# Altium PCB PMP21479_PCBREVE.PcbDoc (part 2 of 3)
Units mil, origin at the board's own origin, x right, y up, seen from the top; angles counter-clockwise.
Board outline 1915.03 x 2932.53 mil, 4 copper layers (Top Layer, Signal Layer 1, Signal Layer 2, Bottom Layer), stack 39.6 mil thick; 137 components, 82 nets, 411 pads, 91 vias.
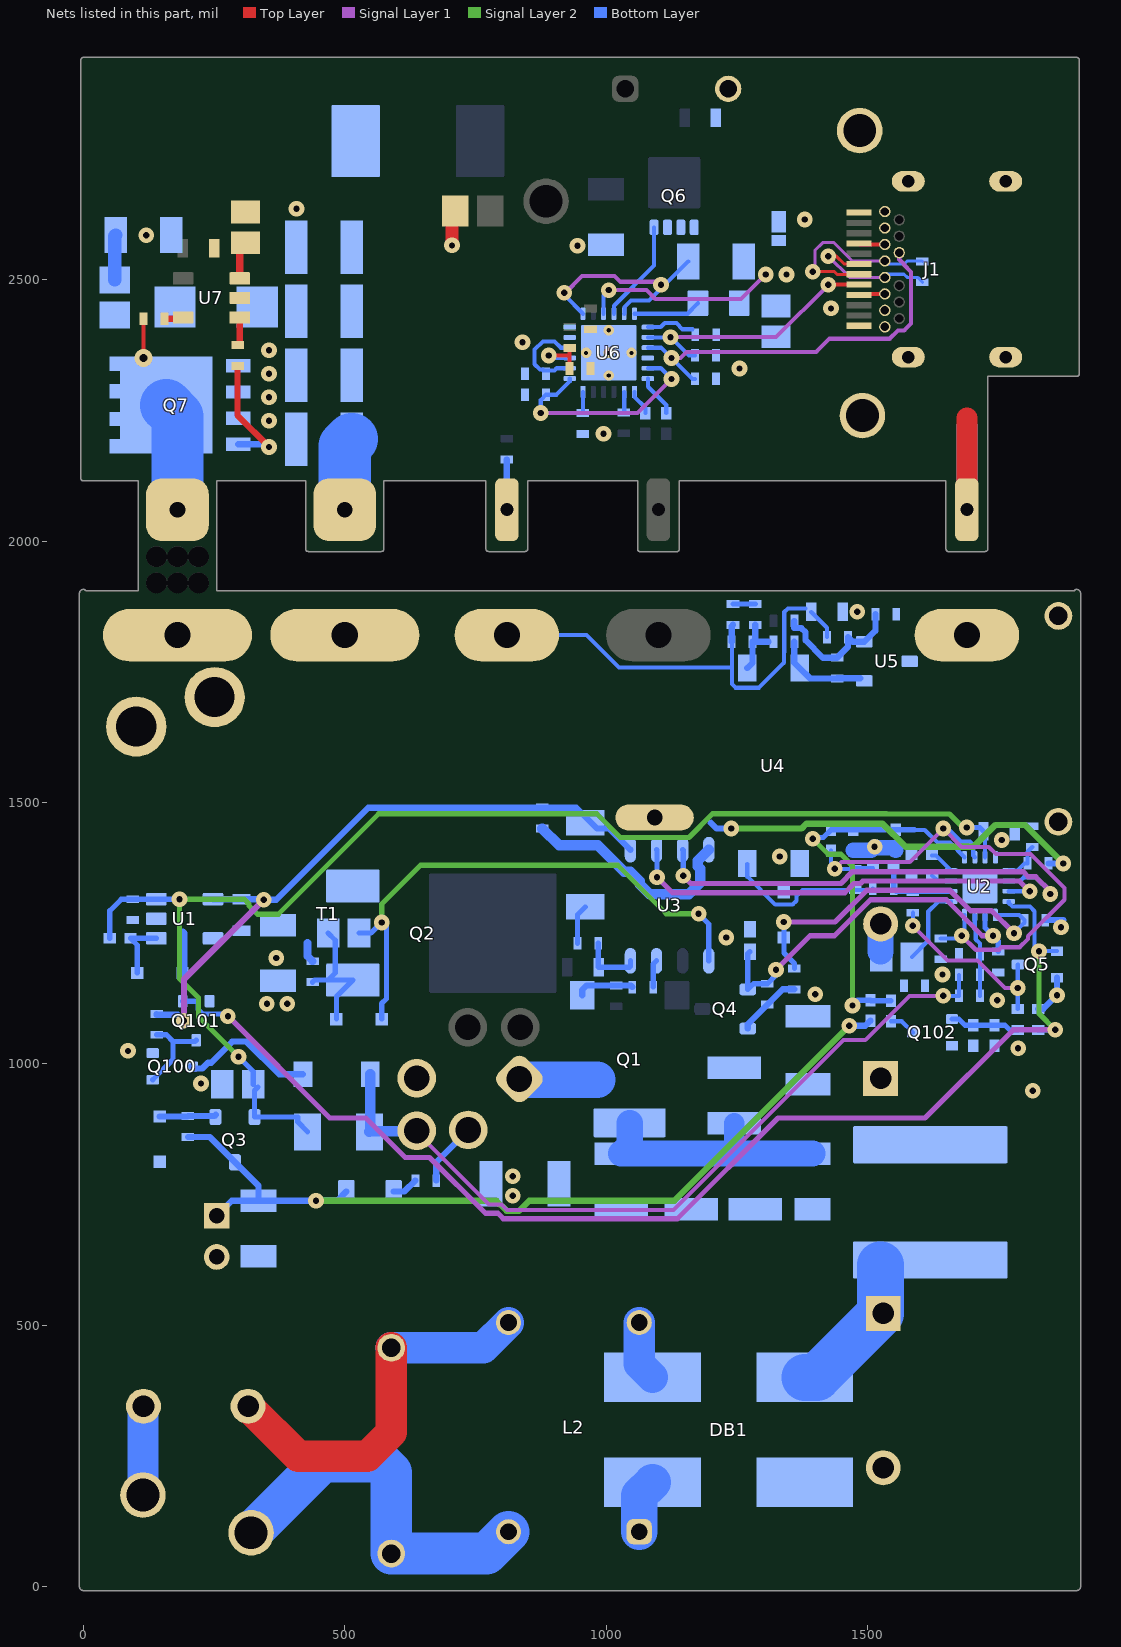
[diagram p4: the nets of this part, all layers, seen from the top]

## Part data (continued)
D3: library part CMP-0029199-1, "Diode, Superfast Rectifier, 200 V, 1 A, 3.5x1.6mm", Manufacturer="Comchip Technology", Supplier Part Number 1=641-1438-1-ND, Value1=1A, Value2=0.95V
D4: library part CMP-0077868-1, "Diode, Standard Recovery Rectifier, 800 V, .2 A, 2x1.4mm", Manufacturer=Rohm, Supplier Part Number 1=RFU02VSM8SCT-ND, Value1=.2A, Value2=2.2V
D5: library part CMP-0005833-2, "Diode, Zener, 15 V, 200 mW, SOD-323", Manufacturer="Diodes Inc.", Power_W=200mW, Supplier Part Number 1=MMSZ5245BS-FDICT-ND, Value1=0.2W
D6: library part CMP-0065112-2, "Diode, TVS, Uni, 18 V, 45 Vc, SOD-323", Manufacturer=Bourns, Supplier Part Number 1=CDSOD323-T18CT-ND, Value1=W
D7: library part CMP-0005884-3, "Diode, Zener, 22 V, 300 mW, SOD-523", Manufacturer="Diodes Inc.", Power_W=300mW, Supplier Part Number 1=BZT52C22T-7DICT-ND, Value1=0.3W
D8: library part CMP-0028829-1, "Diode, Schottky, 30 V, 2 A, 2-XFDFN", Manufacturer="ON Semiconductor", Supplier Part Number 1=NSR20F30NXT5GOSCT-ND, Value1=2A, Value2=0.48V
D9: library part CMP-0005466-2, "Diode, TVS, Bi, 100 V, SMA", Manufacturer=Littelfuse, Power_W=3.3W, Supplier Part Number 1=SMAJ100CALFCT-ND
D100: library part CMP-0029006-2, "Diode, Ultrafast, 100 V, 0.25 A, SOD-323", Manufacturer=Nexperia, Value1=0.25A, Value2=1.4V
D101: library part CMP-0029031-1, "Diode, Switching, 200 V, 0.2 A, SOD-123", Manufacturer="Diodes Inc.", Supplier Part Number 1=BAV21W-FDICT-ND, Value1=0.2A, Value2=1.25V
DB1: "Diode, P-N-Bridge, 600 V, 4 A, Z4-D", Manufacturer="Comchip Technology", Supplier Part Number 1=641-1502-1-ND, Value1=4A, Value2=0.95V
F1: library part CMP-0003561-2, "Fuse, 3.15 A, 250VAC/VDC, TH", Manufacturer=Littelfuse, PartNumber=39213150000, Supplier Part Number 1=F5504CT-ND
J1: library part CMP-0054818-1, "Connector, Receptacle, USB Type C, R/A", Color=Black, Current_A=3A, Manufacturer="Wurth Elektronik", Voltage_V=5V
L1: library part CMP-0084605-1, "Inductor, Shielded, Ferrite, 22 µH, 1.75 A, 0.091 ohm, SMD", Manufacturer="Taiyo Yuden", Value1="0.091 ohm", Value2=1.75A, ValueDisplayed=22µH
L2: library part CMP-0086351-1, "Coupled inductor, 1.3 mH, 0.035 ohm, TH", Manufacturer="Renco Electronics", ValueDisplayed=1.3mH
L3: library part CMP-0062208-1, "Inductor, Shielded, Metal Composite, 330 nH, 21 A, 0.0035 ohm, SMD", Manufacturer=Sumida, Value1="0.003 ohm", Value2=24A, ValueDisplayed=330nH
L100: library part CMP-0086281-1, "Inductor, Wirewound, 1 µH, 0.4 A, 0.091 ohm, SMD", Manufacturer="Taiyo Yuden", Value1="0.091 ohm", Value2=0.4A, ValueDisplayed=1µH
LOGO1: library part IEC_HighVoltage, "IEC 61010-1 High Voltage Warning"
Q1: library part CMP-0086300-1, "MOSFET, N-CH, 700 V, 30 A, PG-SOT223", Alternate Manufacturer=None, Manufacturer="Infineon Technologies", Value1="? ohm", Value2="3.8 nC"
Q2: library part CMP-0079238-1, "MOSFET, N-CH, 600 V, 12 A, DPAK", Alternate Manufacturer=None, Manufacturer="Infineon Technologies", Supplier Part Number 1=IPD60R280P7SAUMA1CT-ND, Value1="? ohm", Value2="18 nC"
Q3: "MOSFET, N-CH, 100 V, 0.17 A, SOT-23", Alternate Manufacturer=None, Manufacturer="Fairchild Semiconductor", Supplier Part Number 1=BSS123NCT-ND, Value1="10 ohm", Value2="1.8 nC"
Q4: library part CMP-0067574-1, "MOSFET, N-CH, 600 V, 0.021 A, AEC-Q101, SOT-23", Alternate Manufacturer=None, Manufacturer="Infineon Technologies", Supplier Part Number 1=BSS126H6327XTSA2CT-ND, Value1="? ohm", Value2="1.4 nC"
Q5: library part CMP-0000643-1, "MOSFET, N-CH, 30 V, 0.18 A, SOT-323", Alternate Manufacturer=None, Manufacturer="NXP Semiconductor", Supplier Part Number 1=568-10508-1-ND, Value1=5, Value2="0.34 nC"
Q6: "MOSFET, N-CH, 30 V, 60 A, DQG0008A", Alternate Manufacturer=None, Manufacturer="Texas Instruments", Supplier Part Number 1=296-39994-1-ND, Value1="0.0032 ohm", Value2="23 nC"
Q7: library part CMP-0001046-2, "MOSFET, N-CH, 150 V, 87 A, PG-TDSON-8", Alternate Manufacturer=None, Manufacturer="Infineon Technologies", Supplier Part Number 1=BSC093N15NS5ATMA1CT-ND, Value2="33 nC"
Q100 Q101 Q102: library part CMP-0000774-1, "MOSFET, N-CH, 60 V, 0.31 A, SOT-323", Alternate Manufacturer=None, Manufacturer="Fairchild Semiconductor", Supplier Part Number 1=2N7002KWCT-ND, Value1=1
R5: library part CMP-0018673-3, "RES, 3.3 M, 5%, 0.25 W, AEC-Q200 Grade 0, 1206", Manufacturer=Vishay-Dale, Power_W=250mW, Supplier Part Number 1=541-3.3MECT-ND, TempCo="200 ppm/C", Tolerance_%=5%, Value2=0.25W, Value_Code=3M30, ValueDisplayed=3.3M
R6: library part CMP-0026721-1, "RES, 100 k, 1%, 0.0625 W, 0402", Manufacturer="Yageo America", Power_W=62.5mW, Supplier Part Number 1=311-100KLRCT-ND, TempCo="100 ppm/C", Tolerance_%=1%, Value2=0.0625W, Value_Code=100k
R7: library part CMP-0026942-3, "RES, 4.7, 5%, 0.063 W, AEC-Q200 Grade 0, 0402", Manufacturer=Vishay-Dale, Power_W=63mW, Supplier Part Number 1=541-4.7JCT-ND, TempCo="200 ppm/C", Tolerance_%=5%, Value2=0.063W, Value_Code=4R70, ValueDisplayed=4.7
R8 R14 R102: library part CMP-0026158-2, "RES, 200 k, 1%, 0.063 W, AEC-Q200 Grade 0, 0402", Manufacturer=Vishay-Dale, Power_W=63mW, Supplier Part Number 1=541-200KLCT-ND, TempCo="100 ppm/C", Tolerance_%=1%, Value2=0.063W, Value_Code=200k
R9: library part CMP-0025997-3, "RES, 130 k, 1%, 0.063 W, AEC-Q200 Grade 0, 0402", Manufacturer=Vishay-Dale, Power_W=63mW, Supplier Part Number 1=541-130KLCT-ND, TempCo="100 ppm/C", Tolerance_%=1%, Value2=0.063W, Value_Code=130k
R10: library part CMP-0026843-3, "RES, 15, 5%, 0.063 W, AEC-Q200 Grade 0, 0402", Manufacturer=Vishay-Dale, Power_W=63mW, Supplier Part Number 1=541-15JCT-ND, TempCo="200 ppm/C", Tolerance_%=5%, Value2=0.063W, Value_Code=15R0, ValueDisplayed=15
R11 R18: library part CMP-0026822-3, "RES, 0, 5%, 0.063 W, AEC-Q200 Grade 0, 0402", Manufacturer=Vishay-Dale, Power_W=63mW, Supplier Part Number 1=541-0.0JCT-ND, TempCo="200 ppm/C", Tolerance_%=5%, Value2=0.063W, Value_Code=0000, ValueDisplayed=0
R12 R16 R100: library part CMP-0026825-5, "RES, 10 k, 5%, 0.063 W, AEC-Q200 Grade 0, 0402", Manufacturer=Vishay-Dale, Power_W=63mW, Supplier Part Number 1=541-10KJCT-ND, TempCo="200 ppm/C", Tolerance_%=5%, Value2=0.063W, Value_Code=10k0, ValueDisplayed=10k
R13: library part CMP-0026399-2, "RES, 48.7 k, 1%, 0.063 W, AEC-Q200 Grade 0, 0402", Manufacturer=Vishay-Dale, Power_W=63mW, Supplier Part Number 1=541-48.7KLCT-ND, TempCo="100 ppm/C", Tolerance_%=1%, Value2=0.063W, Value_Code=48k7, ValueDisplayed=48.7k
R15: library part CMP-0020557-3, "RES, 47, 5%, 0.125 W, AEC-Q200 Grade 0, 0805", Manufacturer=Vishay-Dale, Power_W=125mW, Supplier Part Number 1=541-47ACT-ND, TempCo="200 ppm/C", Tolerance_%=5%, Value2=0.125W, Value_Code=47R0, ValueDisplayed=47
R17: "RES, 1.0 M, 5%, 0.063 W, 0402", Manufacturer=Vishay-Dale, Power_W=0.063, Supplier Part Number 1=541-1.0MJCT-ND, TempCo="200 ppm/C", Tolerance_%=5, Value1=5%, Value2=0.063W, Value_Code=1M00, ValueDisplayed=1.0M
R19: library part CMP-0026095-2, "RES, 1.78 k, 1%, 0.063 W, AEC-Q200 Grade 0, 0402", Manufacturer=Vishay-Dale, Power_W=63mW, Supplier Part Number 1=541-1.78KLCT-ND, TempCo="100 ppm/C", Tolerance_%=1%, Value2=0.063W, Value_Code=1k78, ValueDisplayed=1.78k
R20: library part CMP-0026453-2, "RES, 56.2 k, 1%, 0.063 W, AEC-Q200 Grade 0, 0402", Manufacturer=Vishay-Dale, Power_W=63mW, Supplier Part Number 1=541-56.2KLCT-ND, TempCo="100 ppm/C", Tolerance_%=1%, Value2=0.063W, Value_Code=56k2, ValueDisplayed=56.2k
R21: library part CMP-0017277-2, "RES, 0.15, 1%, 0.5 W, 1206", Manufacturer=Panasonic, Power_W=500mW, Supplier Part Number 1=P16006CT-ND, TempCo="250 ppm/C", Tolerance_%=1%, Value2=0.5W, Value_Code=R150, ValueDisplayed=0.15
R22: library part CMP-0026665-1, "RES, 137 k, 1%, 0.1 W, AEC-Q200 Grade 0, 0402", Manufacturer=Panasonic, Power_W=100mW, Supplier Part Number 1=P137KLCT-ND, TempCo="100 ppm/C", Tolerance_%=1%, Value2=0.1W, Value_Code=137k
R23: library part CMP-0026004-3, "RES, 13.3 k, 1%, 0.063 W, AEC-Q200 Grade 0, 0402", Manufacturer=Vishay-Dale, Power_W=63mW, Supplier Part Number 1=541-13.3KLCT-ND, TempCo="100 ppm/C", Tolerance_%=1%, Value2=0.063W, Value_Code=13k3, ValueDisplayed=13.3k
R24: library part CMP-0025974-3, "RES, 118, 1%, 0.063 W, AEC-Q200 Grade 0, 0402", Manufacturer=Vishay-Dale, Power_W=63mW, Supplier Part Number 1=541-118LCT-ND, TempCo="100 ppm/C", Tolerance_%=1%, Value2=0.063W, Value_Code=118R, ValueDisplayed=118
R25 R31: library part CMP-0026669-1, "RES, 150 k, 1%, 0.1 W, AEC-Q200 Grade 0, 0402", Manufacturer=Panasonic, Power_W=100mW, Supplier Part Number 1=P150KLCT-ND, TempCo="100 ppm/C", Tolerance_%=1%, Value2=0.1W, Value_Code=150k
R26: library part CMP-0026329-2, "RES, 3.01 k, 1%, 0.063 W, AEC-Q200 Grade 0, 0402", Manufacturer=Vishay-Dale, Power_W=63mW, Supplier Part Number 1=541-3.01KLCT-ND, TempCo="100 ppm/C", Tolerance_%=1%, Value2=0.063W, Value_Code=3k01, ValueDisplayed=3.01k
R27: library part CMP-0026022-3, "RES, 150, 1%, 0.063 W, AEC-Q200 Grade 0, 0402", Manufacturer=Vishay-Dale, Power_W=63mW, Supplier Part Number 1=541-150LCT-ND, TempCo="100 ppm/C", Tolerance_%=1%, Value2=0.063W, Value_Code=150R, ValueDisplayed=150
R28: library part CMP-0026196-2, "RES, 24.9 k, 1%, 0.063 W, AEC-Q200 Grade 0, 0402", Manufacturer=Vishay-Dale, Power_W=63mW, Supplier Part Number 1=541-24.9KLCT-ND, TempCo="100 ppm/C", Tolerance_%=1%, Value2=0.063W, Value_Code=24k9, ValueDisplayed=24.9k
R29: library part CMP-0026859-2, "RES, 1.0 M, 5%, 0.063 W, AEC-Q200 Grade 0, 0402", Manufacturer=Vishay-Dale, Power_W=63mW, Supplier Part Number 1=541-1.0MJCT-ND, TempCo="200 ppm/C", Tolerance_%=5%, Value2=0.063W, Value_Code=1M00, ValueDisplayed=1.0M
R30: library part CMP-0026327-2, "RES, 39.2 k, 1%, 0.063 W, AEC-Q200 Grade 0, 0402", Manufacturer=Vishay-Dale, Power_W=63mW, Supplier Part Number 1=541-39.2KLCT-ND, TempCo="100 ppm/C", Tolerance_%=1%, Value2=0.063W, Value_Code=39k2, ValueDisplayed=39.2k
R32 R47: library part CMP-0026027-3, "RES, 15.0 k, 1%, 0.063 W, AEC-Q200 Grade 0, 0402", Manufacturer=Vishay-Dale, Power_W=63mW, Supplier Part Number 1=541-15.0KLCT-ND, TempCo="100 ppm/C", Tolerance_%=1%, Value2=0.063W, Value_Code=15k0, ValueDisplayed=15.0k
R33: library part CMP-0026435-2, "RES, 511 k, 1%, 0.063 W, AEC-Q200 Grade 0, 0402", Manufacturer=Vishay-Dale, Power_W=63mW, Supplier Part Number 1=541-511KLCT-ND, TempCo="100 ppm/C", Tolerance_%=1%, Value2=0.063W, Value_Code=511k
R34: "RES, 0.005, 1%, 0.25 W, 1206", Manufacturer=Vishay-Dale, Power_W=0.25, Supplier Part Number 1=WSLC-.005CT-ND, TempCo="110 ppm/C", Tolerance_%=1, Value1=1%, Value2=0.25W, Value_Code=5L000, ValueDisplayed=0.005
R35: "RES, 100, 5%, 0.063 W, 0402", Manufacturer=Vishay-Dale, Power_W=0.063, Supplier Part Number 1=541-100JCT-ND, TempCo="200 ppm/C", Tolerance_%=5, Value1=5%, Value2=0.063W, Value_Code=100R, ValueDisplayed=100
R36: "RES, 100 k, 1%, 0.063 W, 0402", Manufacturer=Vishay-Dale, Power_W=0.063, Supplier Part Number 1=541-100KLCT-ND, TempCo="100 ppm/C", Tolerance_%=1, Value1=1%, Value2=0.063W, Value_Code=100k
R37: "RES, 140 k, 1%, 0.063 W, 0402", Manufacturer=Vishay-Dale, Power_W=0.063, Supplier Part Number 1=541-140KLCT-ND, TempCo="100 ppm/C", Tolerance_%=1, Value1=1%, Value2=0.063W, Value_Code=140k
R38: "RES, 86.6 k, 1%, 0.063 W, 0402", Manufacturer=Vishay-Dale, Power_W=0.063, Supplier Part Number 1=541-86.6KLCT-ND, TempCo="100 ppm/C", Tolerance_%=1, Value1=1%, Value2=0.063W, Value_Code=86k6, ValueDisplayed=86.6k
R39: "RES, 120, 0.1%, 0.125 W, 0805", Manufacturer="Susumu Co Ltd", Power_W=0.125, Supplier Part Number 1=RG20P120BCT-ND, TempCo="25 ppm/C", Tolerance_%=0.1, Value1=0.1%, Value2=0.125W, Value_Code=120R, ValueDisplayed=120
R40: library part CMP-0025702-4, "RES, 10 M, 5%, 0.1 W, AEC-Q200 Grade 0, 0603", Manufacturer=Vishay-Dale, Power_W=100mW, Supplier Part Number 1=541-10MGCT-ND, TempCo="200 ppm/C", Tolerance_%=5%, Value2=0.1W, Value_Code=10M0, ValueDisplayed=10M
R41: library part CMP-0018603-3, "RES, 1.0 k, 5%, 0.25 W, AEC-Q200 Grade 0, 1206", Manufacturer=Vishay-Dale, Power_W=250mW, Supplier Part Number 1=541-1.0KECT-ND, TempCo="200 ppm/C", Tolerance_%=5%, Value2=0.25W, Value_Code=1k00, ValueDisplayed=1.0k
R42 R43: library part CMP-0026827-3, "RES, 10, 5%, 0.063 W, AEC-Q200 Grade 0, 0402", Manufacturer=Vishay-Dale, Power_W=63mW, Supplier Part Number 1=541-10JCT-ND, TempCo="200 ppm/C", Tolerance_%=5%, Value2=0.063W, Value_Code=10R0, ValueDisplayed=10
R44 R45: library part CMP-0027004-2, "RES, 0, 5%, 0.063 W, 0402", Manufacturer="Yageo America", Power_W=63mW, Supplier Part Number 1=311-0.0JRCT-ND, TempCo="200 ppm/C", Tolerance_%=5%, Value2=0.063W, Value_Code=0000, ValueDisplayed=0
R46: library part CMP-0026510-2, "RES, 69.8 k, 1%, 0.063 W, AEC-Q200 Grade 0, 0402", Manufacturer=Vishay-Dale, Power_W=63mW, Supplier Part Number 1=541-69.8KLCT-ND, TempCo="100 ppm/C", Tolerance_%=1%, Value2=0.063W, Value_Code=69k8, ValueDisplayed=69.8k
R101: library part CMP-0025950-3, "RES, 100 k, 1%, 0.063 W, AEC-Q200 Grade 0, 0402", Manufacturer=Vishay-Dale, Power_W=63mW, Supplier Part Number 1=541-100KLCT-ND, TempCo="100 ppm/C", Tolerance_%=1%, Value2=0.063W, Value_Code=100k
R103: library part CMP-0026280-2, "RES, 301 k, 1%, 0.063 W, AEC-Q200 Grade 0, 0402", Manufacturer=Vishay-Dale, Power_W=63mW, Supplier Part Number 1=541-301KLCT-ND, TempCo="100 ppm/C", Tolerance_%=1%, Value2=0.063W, Value_Code=301k
R104: library part CMP-0026100-2, "RES, 1.00 M, 1%, 0.063 W, AEC-Q200 Grade 0, 0402", Manufacturer=Vishay-Dale, Power_W=63mW, Supplier Part Number 1=541-1.00MLCT-ND, TempCo="100 ppm/C", Tolerance_%=1%, Value2=0.063W, Value_Code=1M00, ValueDisplayed=1.00M
RT1: library part CMP-0002532-2, "Thermistor NTC, 100k ohm, 5%, 0805", Manufacturer=MuRata, Power_W=200mW, Supplier Part Number 1=490-2451-1-ND, Tolerance_%=5%
T1: library part CMP-0081439-3, "Transformer, 110 uH, TH", Manufacturer="Renco Electronics", ValueDisplayed=110µH
TP1 TP4: library part CMP-0055148-1, "Test Point, Multipurpose, Black, TH", Color=Black, Manufacturer=Keystone, PartNumber=5011, Supplier Part Number 1=36-5011-ND
TP2: library part CMP-0055149-1, "Test Point, Multipurpose, White, TH", Color=White, Manufacturer=Keystone, PartNumber=5012, Supplier Part Number 1=36-5012-ND
TP3 TP5: library part CMP-0055147-1, "Test Point, Multipurpose, Red, TH", Color=Red, Manufacturer=Keystone, PartNumber=5010, Supplier Part Number 1=36-5010-ND
U1: library part CMP-0066933-1, "50-mA 40-V Voltage-Tracking LDO With 5-mV Tracking Tolerance, DBV0005A (SOT-23-5)", Alternate Manufacturer="Texas Instruments"
U2: library part CMP-0014005-4, "Active-Clamp Flyback Controller, RTE0016C (WQFN-16)", Alternate Manufacturer="Texas Instruments", Alternate PartNumber=UCC28780RTE
U3: library part CMP-0065069-2, "620-V High-Side Low-Side Gate Driver with 0.5/1.0A Peak Output and RobustDrive, D0008B (SOIC-8)", Alternate Manufacturer="Texas Instruments", Alternate PartNumber=UCC27710D
U4: library part CMP-0006160-3, "Optocoupler, 5 kV, 63-125% CTR, SMT", Manufacturer=Vishay-Semiconductor, Supplier Part Number 1=VOL618A-2TCT-ND, Voltage_Isolation_Vrms=5kV
U5: library part CMP-0066199-1, "2.5V Low Iq Adjustable Precision Shunt Regulator, DBZ0003A (SOT-23-3)", Alternate Manufacturer="Texas Instruments"
U6: "USB Type-C and USB PD Source Controller, RGE0024H (VQFN-24)", Alternate Manufacturer="Texas Instruments", Alternate PartNumber=TPS25740BRGET
U7: library part CMP-0013047-3, "High-Frequency Multi-Mode Synchronous Rectifier Controller, DBV0005A (SOT-23-5)", Alternate Manufacturer="Texas Instruments", Alternate PartNumber=UCC24612-2DBVR

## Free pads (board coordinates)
  oval 285x100 hole 50 slot 200 at 0 deg: 0(180,1820) 0(500,1820)
  oval 200x100 hole 50 slot 120 at 0 deg: 0(810,1820) 0(1100,1820) 0(1690,1820)
  oval 150x50 hole 30 slot 110 at 0 deg: 0(1092.72,1471.05)
  round 40 hole 40 unplated: 1(140,1920) 1(140,1970) 1(180,1920) 1(180,1970) 1(220,1920) 1(220,1970)
  rrect50% 120x120 hole 30: 2(180,2060) 2(500,2060)
  rrect50% 45x120 hole 25: 2(810,2060) 2(1100,2060) 2(1690,2060)

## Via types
v1: diameter 30, hole 12, Top Layer to Bottom Layer, 44 vias
v2: diameter 30, hole 12, Top Layer to Bottom Layer, tented both sides, 31 vias
v3: diameter 19.68, hole 7.87, Top Layer to Bottom Layer, 11 vias
v4: diameter 30, hole 12, Top Layer to Bottom Layer, tented bottom, 2 vias
v5: diameter 19.68, hole 7.87, Top Layer to Bottom Layer, tented both sides, 1 vias
v6: diameter 30, hole 12, Top Layer to Bottom Layer, tented top, 1 vias
v7: diameter 34, hole 16, Top Layer to Bottom Layer, 1 vias

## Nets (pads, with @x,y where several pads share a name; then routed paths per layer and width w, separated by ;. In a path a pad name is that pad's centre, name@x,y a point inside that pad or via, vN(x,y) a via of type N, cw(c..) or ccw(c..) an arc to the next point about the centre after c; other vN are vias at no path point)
CC1: C33.1 J1.A5 U6.2 | length 506.1
  Top Layer w8: v1(1425,2490) 1425.47,2490.47 J1.A5@1483.46,2490.47
  Signal Layer 1 w8: v1(1123.21,2390) 1325,2390 v1(1425,2490)
  Bottom Layer w8: U6.2@1079.8,2389.53 v1@1122.74,2389.53 ; v1(1123.21,2390) 1158.21,2355 C33.1@1170,2355
CC2: C34.1 J1.B5 U6.3 | length 745.5
  Signal Layer 1 w8: v1(1125,2350) 1141.99,2350 1153.87,2361.87 1401.7,2361.87 1426.89,2387.06 1542.47,2387.06 1558.22,2402.81 1570.03,2402.81 1583.33,2416.11 1583.33,2514.8 1569.62,2528.51 1569.62,2529.8 1560.63,2538.78 J1.B5@1560.63,2551.5
  Bottom Layer w8: U6.3@1079.8,2369.84 1105.16,2369.84 v1(1125,2350) 1165,2310 C34.1@1170,2310
CTL1: R47.2 U6.6 | length 80.4
  Bottom Layer w8: U6.6@1079.8,2310.79 1079.8,2295.2 1115,2260 R47.2@1115,2245
CTL2: R46.2 U6.7 | length 48.8
  Bottom Layer w8: U6.7@1054.21,2285.2 1054.21,2275.79 1075,2255 R46.2@1075,2245
CTL3: R45.1 U6.8 | length 39.7
  Bottom Layer w8: R45.1@1034.53,2245.47 U6.8@1034.53,2285.2
DN: J1.A7 J1.B7 R35.1 | length 273.9
  Top Layer w6: v1(1425,2545) 1440,2545 1455.16,2529.84 J1.A7@1483.46,2529.84
  Signal Layer 1 w6: v1(1425,2545) 1465.75,2504.25 J1.B7@1533.07,2504.25
  Bottom Layer w6: J1.B7@1533.07,2504.25 1533.07,2510.2 1569.62,2510.2 1575.57,2504.25 1595.75,2504.25 R35.1@1605,2495
DP: J1.A6 J1.B6 R35.2 | length 369.1
  Top Layer w6: v1(1395,2515) 1395.87,2515.87 1435.72,2515.87 1441.43,2510.16 J1.A6@1483.46,2510.16
  Signal Layer 1 w6: v1(1395,2515) 1399.13,2519.13 1399.13,2555.72 1414.28,2570.87 1435.72,2570.87 1470.84,2535.75 J1.B6@1533.07,2535.75
  Bottom Layer w6: J1.B6@1533.07,2535.75 1533.07,2529.8 1569.62,2529.8 1575.57,2535.75 1604.25,2535.75 R35.2@1605,2535
FB: C14.2 R30.1 R33.2 U2.10 | length 141.8
  Bottom Layer w10: C14.2@1550,1365 R30.1@1550,1335 1555,1330 1580,1330 1625,1330 ; 1625.16,1330.16 U2.10@1659.88,1330.16
ICGND: C10.2 C12.2 C13.2 C21.2 C23.2 C101.2 Q102.2 R8.1 R9.1 R13.1 R18.2 R23.1 R102.1 U2.16 U2.17@1715,1340 | length 86.9
  Bottom Layer w30: R13.1@1472.39,1408.45 1506.9,1408.45 v1(1513.45,1415) 1515.19,1413.26 1549.2,1413.26 C13.2@1553.89,1408.57
  other v1: 1787.96,1029.71 1747.99,1121.82 1643.2,1170.91
  other v2: 1756.67,1428.13
NetC1_1: C1.1 DB1.1 L1.1 | length 288.1
  Bottom Layer w90: DB1.1@1379.89,400.39 1402.76,400.39 1525,522.64 L1.1@1525,615
NetC3_1: C3.1 F1.1 L2.4 | length 738.6
  Top Layer w60: F1.1@315,345 410.72,249.28 543.35,249.28 589,294.93 C3.1@589,456.85
  Bottom Layer w60: C3.1@589,456.85 765.04,456.85 L2.4@813.19,505
NetC3_2: C3.2 L2.2 TP2.1 | length 729.4
  Bottom Layer w80: TP2.1@321,103 456.71,238.71 568.77,238.71 589,218.47 C3.2@589,63.15 771.34,63.15 L2.2@813.19,105
NetC6_2: C6.2 C7.2 C8.2 C9.2 Q1.2 R5.1 | length 492
  Bottom Layer w40: C6.2@1240,828.15 1245,833.15 C8.2@1245,886.35
  Bottom Layer w50: Q1.2@1045,887.11 1045,844.23 C9.2@1028.92,828.15 1240,828.15 R5.1@1395,828.15
NetC11_1: C11.1 R7.2 U3.8 | length 118
  Bottom Layer w10: R7.2@985,1230.73 985,1185.58 C11.1@985.79,1184.79 1044.47,1184.79 1046.32,1186.65 U3.8@1046.32,1197.06
NetC13_1: C13.1 R13.2 R14.1 R101.2 R104.1 U2.13 | length 762.8
  Signal Layer 2 w10: v2(1395,1430.49) 1424.66,1400.84 1448.99,1400.84 1471.12,1378.71 v2(1471.12,1111.61)
  Bottom Layer w8: 1589.76,1447.57 1609.43,1447.57 1633.87,1423.13 1657.46,1423.13 U2.13@1685.47,1395.12
  Bottom Layer w10: v2(1395,1430.49) 1397.39,1432.88 1415.31,1432.88 R14.1@1430,1447.57 1430.25,1447.82 R13.2@1472.39,1447.82 1472.52,1447.94 C13.1@1553.89,1447.94 1554.26,1447.57 1589.76,1447.57 ; v2(1471.12,1111.61) 1481.32,1121.82 R104.1@1505.5,1121.82 1506.46,1120.86 R101.2@1545,1120.86
NetC17_2: C17.2 C18.1 C102.2 D1.2 Q2.3 R16.1 R19.2 R21.2 U1.2 U1.5 U3.4 | length 1333.6
  Signal Layer 2 w12: v2(1239.29,1450) 1373.67,1450 1383.04,1459.37 1528.58,1459.37 1572.94,1415 1702.71,1415 1744.71,1457.01 1800.85,1457.01 v2(1874.55,1383.31)
  Bottom Layer w12: 1200.2,1461.13 1211.32,1450 v2(1239.29,1450) ; R19.2@1846.14,1383.31 v2(1874.55,1383.31)
  Bottom Layer w15: 428.94,1231.41 428.94,1205.79 R16.1@438.51,1196.22
  Bottom Layer w20: D1.2@189.57,1173.62 189.57,1249.14 ; C102.2@877.65,1450 909.81,1417.84 983.77,1417.84 1034.43,1367.18 1046.32,1367.18 1064.38,1349.12 1064.38,1343.26 1083.64,1324 1158.06,1324 1180.13,1346.07 1180.13,1373.3 1175.49,1377.94 1175.49,1388.83 U3.4@1196.32,1409.66
NetC20_2: C20.2 R20.1 R23.2 U2.7 | length 159
  Bottom Layer w8: U2.7@1705.16,1284.88 1705.16,1257.85 1706.87,1256.13 1706.87,1238.13 1715,1230 R23.2@1715,1210 R20.1@1715,1170 C20.2@1715,1130
NetC21_1: C21.1 R19.1 U2.1 | length 76.6
  Bottom Layer w8: U2.1@1770.12,1369.53 1786.65,1369.53 1800.43,1383.31 R19.1@1806.14,1383.31 1806.14,1405.67 C21.1@1815,1414.54
NetC23_1: C23.1 D7.1 Q4.1 R22.2 U2.6 | length 729.1
  Signal Layer 1 w10: v2(1325,1180) 1390,1245 1436.83,1245 1505.81,1313.98 1650.44,1313.98 1719.42,1245 v1(1740,1245)
  Bottom Layer w10: D7.1@1275,1214.56 1270.8,1210.36 Q4.1@1270.8,1142.32 1281.76,1153.28 R22.2@1308.42,1153.28 1325,1169.86 v2(1325,1180) ; U2.6@1724.84,1284.88 1724.84,1260.16 v1(1740,1245) 1750,1235 C23.1@1750,1215
NetC24_2: C24.2 D6.1 R24.1 U2.5 | length 689.8
  Signal Layer 1 w10: v2(1339.48,1271.3) 1437.85,1271.3 1498.4,1331.85 1657.85,1331.85 1696.74,1292.96 1737.04,1292.96 v4(1780,1250)
  Bottom Layer w8: U2.5@1744.53,1284.88 1790.12,1284.88 C24.2@1800,1275 1800,1270 v4(1780,1250)
  Bottom Layer w10: v2(1339.48,1271.3) 1340,1270.77 D6.1@1340,1241.79 1340,1211.85 1360,1191.85 R24.1@1360,1182.4
NetC25_2: C25.2 R27.2 | length 42.4
  Bottom Layer w10: C25.2@1242.59,1879.64 R27.2@1285,1879.64
NetC27_1: C27.1 R25.1 R28.2 R31.1 U5.2 | length 271.8
  Bottom Layer w12: R28.2@1360,1847.15 1360,1833.47 1373.25,1833.47 1381.37,1825.35 1381.37,1810.29 1414.66,1777.01 C27.1@1441.58,1777.01 1462.55,1797.97 R25.1@1462.55,1816.15 1471.43,1807.27 U5.2@1493.88,1807.27 1515,1828.39 R31.1@1515,1860
NetC27_2: C27.2 R32.1 U4.2 U5.1 | length 179.5
  Bottom Layer w12: R32.1@1360,1807.6 1360,1767.01 U4.2@1370,1757.01 1390,1737.01 C27.2@1441.58,1737.01 1442.17,1737.6 U5.1@1486.19,1737.6
NetC30_1: C30.1 U6.5 U6.13 | length 431
  Signal Layer 1 w8: v1(875,2245) 1060,2245 v1(1125,2310)
  Bottom Layer w8: v1(875,2245) 875,2270 C30.1@885,2280 905,2280 930.2,2305.2 U6.13@930.2,2310.79 ; U6.5@1079.8,2330.47 1104.53,2330.47 v1(1125,2310)
NetC31_1: C31.1 U6.14 U6.16 | length 181.6
  Bottom Layer w8: U6.14@930.2,2330.47 905.47,2330.47 901.13,2326.13 878.87,2326.13 878.87,2328.13 873.17,2328.13 863.13,2338.17 863.13,2366.13 878.87,2381.87 901.13,2381.87 913.16,2369.84 U6.16@930.2,2369.84
NetC32_1: C32.1 U6.1 | length 93.3
  Bottom Layer w8: U6.1@1079.8,2409.21 1104.42,2409.21 1112.08,2416.87 1134.34,2416.87 1146.21,2405 C32.1@1165,2405
NetC41_2: C41.2 R41.2 | length 86.3
  Bottom Layer w25: C41.2@60,2499.49 60,2583.15 R41.2@61.85,2585
NetC42_2: C42.2 U7.3 | length 53.3
  Top Layer w15: U7.3@299.13,2502.4 C42.2@299.13,2555.67
NetC100_1: C100.1 Q5.3 R33.1 | length 360
  Signal Layer 1 w8: v2(1586.62,1264) 1652.84,1197.78 1710.04,1197.78 1762.82,1145 v2(1787.15,1145)
  Bottom Layer w8: v2(1586.62,1264) 1586.62,1288.82 R33.1@1586.76,1288.97 ; C100.1@1787.15,1105 v2(1787.15,1145) 1787.15,1189.55 Q5.3@1787.6,1190
NetC101_1: C101.1 Q102.1 R102.2 R103.1 | length 134.3
  Bottom Layer w10: Q102.1@1661.57,1085.59 1674.36,1085.59 1686.29,1073.66 C101.1@1702.42,1073.66 R102.2@1742.95,1073.66 1763.07,1073.66 1772.1,1064.63 R103.1@1787.15,1064.63
NetD1_1: D1.1 R6.1 U1.1 | length 121.5
  Bottom Layer w10: D1.1@102.95,1173.62 102.95,1227.17 R6.1@90,1240.12 U1.1@139.61,1240.12
NetD2_1: D2.1 R7.1 | length 75.6
  Bottom Layer w10: R7.1@945,1230.73 945,1285.1 D2.1@960,1300.1
NetD4_2: D4.2 R11.2 | length 50.2
  Bottom Layer w12: D4.2@593.46,755.78 614.09,755.78 R11.2@635,776.69
NetD5_1: D5.1 Q3.1 R17.2 | length 108.3
  Bottom Layer w12: D5.1@146.26,899.33 199.33,899.33 R17.2@200,900 250.91,900 Q3.1@253.31,902.4
NetD100_1: D100.1 R15.1 U3.5 | length 1052.9
  Signal Layer 2 w10: v2(570.53,1270.47) 570.53,1305.36 645.08,1379.92 1022.19,1379.92 1115.06,1287.05 v2(1176.81,1287.05)
  Bottom Layer w10: R15.1@527.22,1250 550.05,1250 v2(570.53,1270.47) 579.7,1261.3 579.7,1124.51 570.53,1115.34 D100.1@570.53,1085.59 ; v2(1176.81,1287.05) 1196.32,1267.54 U3.5@1196.32,1197.06
NetD100_2: D100.2 Q2.1 R15.2 R16.2 | length 267.6
  Bottom Layer w10: R16.2@438.51,1156.22 442.53,1160.24 Q2.1@468.54,1160.24 ; R15.2@468.16,1250 481.92,1236.24 481.92,1173.62 Q2.1@468.54,1160.24 ; D100.2@483.91,1085.59 483.91,1128.51 Q2.1@515.64,1160.24 Q2.1@468.54,1160.24
NetD101_1: D101.1 Q100.3 | length 262
  Bottom Layer w12: Q100.3@207.4,995 212.16,990.24 213.04,991.13 227.25,991.13 238.34,1002.21 244.33,1002.21 284.65,1042.53 311.87,1042.53 374.41,980 D101.1@419.84,980
NetDB1_2: DB1.2 L2.3 | length 115.1
  Bottom Layer w60: L2.3@1063.19,505 1063.19,425.76 DB1.2@1088.56,400.39
NetDB1_3: DB1.3 L2.1 | length 105.1
  Bottom Layer w70: L2.1@1063.19,105 1063.19,174.24 DB1.3@1088.56,199.61
NetF1_2: F1.2 TP1.1 | length 170.4
  Bottom Layer w60: TP1.1@114,175 114,344 F1.2@115,345
NetQ1_1: Q1.1 R10.2 R12.2 | length 110.6
  Bottom Layer w12: Q1.1@954.45,1131.2 954.45,1141.4 963.05,1150 R12.2@1019.18,1150 1046.9,1150 R10.2@1050,1146.9
NetQ4_2: Q4.2 R22.1 R24.2 | length 125
  Bottom Layer w12: Q4.2@1270.8,1067.52 1270.8,1075.66 R22.1@1308.42,1113.28 1337.54,1142.4 R24.2@1360,1142.4
NetQ6_1: Q6.1 Q6.2 Q6.3 R34.2 U6.19 U6.23 | length 431.3
  Signal Layer 1 w8: v1(920,2475) 921.99,2475 953.87,2506.87 1016.13,2506.87 1027.13,2495.87 1099.13,2495.87 v1(1105,2490)
  Bottom Layer w8: v1(920,2475) 920,2470.59 U6.19@955.79,2434.8 ; U6.23@1034.53,2434.8 1035,2435.28 1035,2447.76 1047.24,2460 1081.85,2460 R34.2@1156.85,2535
NetQ6_4: Q6.4 U6.22 | length 197
  Bottom Layer w8: U6.22@1014.84,2434.8 1014.84,2450.05 1091.61,2526.82 Q6.4@1091.61,2599.96
NetQ7_4: Q7.4 R43.2 | length 240.7
  Top Layer w12: R43.2@295,2335 295,2240 v1(355,2180)
  Bottom Layer w12: Q7.4@296.22,2185 350,2185 v1(355,2180)
NetQ100_1: Q100.1 Q101.3 R100.1 | length 171.3
  Bottom Layer w10: Q100.1@132.6,969.41 171.42,1008.23 171.42,1042.81 ; R100.1@140,1055.5 158.72,1055.5 171.42,1042.81 ; Q101.3@215.7,1045 213.51,1042.81 171.42,1042.81
NetQ102_3: Q102.3 R101.1 | length 50.7
  Bottom Layer w8: R101.1@1545,1081.49 1565.27,1081.49 Q102.3@1586.76,1060
NetR8_2: R8.2 U2.11 | length 40.8
  Bottom Layer w8: R8.2@1623.49,1360.52 1634.17,1349.84 U2.11@1659.88,1349.84
NetR9_2: R9.2 U2.12 | length 48.7
  Bottom Layer w8: R9.2@1623.04,1398.2 1631.2,1398.2 U2.12@1659.88,1369.53
NetR10_1: R10.1 U3.7 | length 52.8
  Bottom Layer w10: R10.1@1090,1146.9 1090,1190.74 U3.7@1096.32,1197.06
NetR11_1: R11.1 T1.5 | length 120.4
  Bottom Layer w12: R11.1@675,776.69 675,811.79 T1.5@735.31,872.1
NetR26_1: R26.1 R27.1 R32.2 U4.1 | length 119.1
  Bottom Layer w12: U4.1@1270,1757.01 1280,1767.01 R26.1@1280,1807.5 R26.1@1280.1,1807.6 ; R27.1@1285,1839.64 1285,1812.5 R26.1@1280.1,1807.6 ; 1310.35,1807.6 R26.1@1280.1,1807.6
NetR29_1: R29.1 R30.2 U4.4 | length 304
  Bottom Layer w8: U4.4@1270,1381.93 1270,1357.99 1323.27,1304.72 1356.73,1304.72 1364.04,1312.03 1364.04,1321.35 1375.28,1332.58 R29.1@1476.03,1332.58 1507.58,1332.58 R30.2@1510,1335
NetR36_2: R36.2 U6.12 | length 39.4
  Bottom Layer w8: R36.2@955.79,2245.79 U6.12@955.79,2285.2
NetR37_1: R37.1 R38.2 U6.15 | length 114.7
  Top Layer w8: v1(890,2355) 930,2355 ; R38.2@930,2330 930,2355 ; R37.1@930,2369.33 930,2355
  Bottom Layer w8: v1@894.84,2350.16 U6.15@930.2,2350.16
NetR39_1: R39.1 U6.24 | length 129.8
  Bottom Layer w8: U6.24@1054.21,2434.8 1155.43,2434.8 R39.1@1175.63,2455
NetR42_1: R42.1 U7.5 | length 33.3
  Top Layer w12: R42.1@155,2425 U7.5@188.27,2425
NetR43_1: R43.1 U7.1 | length 54.3
  Top Layer w12: R43.1@295,2375 299.13,2379.13 U7.1@299.13,2427.6
NetRT1_1: RT1.1 U2.9 | length 151.4
  Bottom Layer w8: RT1.1@1585,1204.4 1616.13,1235.53 1616.13,1291.13 1635.47,1310.47 U2.9@1659.88,1310.47
OPTOTOP: pad.2@810,2060 R44.2 | length 95.8
  Bottom Layer w12: pad.2@810,2060 R44.2@810,2155.79
OPTOTOP1: C25.1 C26.2 pad.0@810,1820 R25.2 R26.2 | length 895.5
  Bottom Layer w8: pad.0@810,1820 962.5,1820 1024.37,1758.13 1238.54,1758.13 1240.41,1760 ; R26.2@1240,1807.5 1240.41,1807.5 1240.41,1760 ; 1381.4,1871.02 1347.58,1871.02 1340.63,1864.06 1340.63,1787.73 1340.41,1787.52 1340.41,1767.32 1292.63,1719.54 1247.37,1719.54 1240.41,1726.5 1240.41,1760 ; C26.2@1392.24,1864.5 1422.55,1834.2 R25.2@1422.55,1816.15
  Bottom Layer w12: R26.2@1240,1807.5 1240,1837.05 C25.1@1242.59,1839.64
PGND: C1.2 C2.2 C4.1 C5.1 C15.2 C16.2 C22.1 C24.1 C44.2 C100.2 D5.2 D6.2 D7.2 DB1.4 pad.0@1092.72,1471.05 Q5.2 Q100.2 Q101.2 R18.1 R21.1 RT1.2 T1.7 U4.3 | length 167.5
  Bottom Layer w12: C100.2@1826.52,1105 1836.06,1105 v1(1862.26,1131.2) 1862.4,1131.35 Q5.2@1862.4,1164.41 ; C24.1@1840,1275 v6@1875,1275
  Bottom Layer w50: RT1.2@1525,1214.96 C2.2@1525,1267.64
  other v1: 1816.14,948.64 225,962.25 85.26,1024.74 1229.88,1241.62 1331.81,1396.41
  other v2: 821.43,747.56 821.43,784.86 351.03,1115 390,1114.71 368.91,1202.4
  other v4: 1400,1133.08
  other v6: 1870,1261.22
PWMH: U2.3 U3.2 | length 835.4
  Signal Layer 1 w10: v2(1097.26,1356.87) 1126.92,1327.21 1456.4,1327.21 1474.27,1345.09 1486.36,1345.09 1491,1349.72 1790.28,1349.72 v2(1810,1330)
  Bottom Layer w8: U2.3@1770.12,1330.16 v2@1809.84,1330.16
  Bottom Layer w10: U3.2@1096.32,1409.66 1097.26,1408.72 v2(1097.26,1356.87)
PWML: U2.2 U3.3 | length 886.2
  Signal Layer 1 w10: v2(1147.26,1359.69) 1161.85,1345.09 1448.99,1345.09 1471.51,1367.6 1797.68,1367.6 1807.4,1357.87 1821.55,1357.87 1849.69,1329.73 v2(1849.69,1325.02)
  Bottom Layer w8: U2.2@1770.12,1349.84 1791.84,1349.84 1798.87,1356.87 1821.13,1356.87 1849.69,1328.31 v2(1849.69,1325.02)
  Bottom Layer w10: U3.3@1146.32,1409.66 1147.26,1408.72 v2(1147.26,1359.69)
REF: C12.1 C14.1 R14.2 R29.2 U2.8 U2.14 | length 1082.3
  Signal Layer 1 w8: v1(1437.45,1372.96) 1450.31,1385.83 1580.83,1385.83 v2(1645,1450) 1680,1415 1731.8,1415 1745.54,1401.26 1811.46,1401.26 1876.57,1336.16 1876.57,1313.89 1806.87,1244.2 1806.87,1238.87 1791.13,1223.13 1756.13,1223.13 1751.13,1218.13 1706.87,1218.13 v1(1680,1245)
  Bottom Layer w8: R14.2@1430,1408.2 1430,1380.41 v1(1437.45,1372.96) 1437.83,1372.58 R29.2@1476.03,1372.58 1477.47,1374.02 C14.1@1510.32,1374.02 ; C12.1@1640,1240 1675,1240 v1(1680,1245) 1685.47,1250.47 U2.8@1685.47,1284.88 ; v2(1645,1450) 1653.62,1450 1678.34,1425.28 1696.02,1425.28 1702.07,1419.23 1702.07,1398.2 U2.14@1705.16,1395.12
RUN: Q5.1 Q101.1 R103.2 U2.4 | length 2368.8
  Signal Layer 1 w10: v2(276.42,1091.26) 471.27,896.42 540.18,896.42 615.7,820.9 662.24,820.9 769,714.14 792.99,714.14 803.31,703.81 1135.82,703.81 1328.42,896.42 1610,896.42 1778.58,1065 v2(1858.97,1065)
  Signal Layer 2 w10: v2(1828.03,1215.59) 1828.03,1095.95 v2(1858.97,1065)
  Bottom Layer w8: U2.4@1770.12,1310.47 1770.12,1307.87 1777.24,1300.76 1810.54,1300.76 1819.37,1291.92 1819.37,1224.24 v2(1828.03,1215.59) Q5.1@1862.4,1215.59
  Bottom Layer w10: Q101.1@190.11,1119.8 217.11,1119.8 219.17,1117.74 219.17,1103.8 227.84,1095.12 272.57,1095.12 v2(276.42,1091.26) v2@275.66,1090.5 ; R103.2@1826.52,1064.63 1858.6,1064.63 v2(1858.97,1065)
SGND: C28.2 C29.2 C30.2 C31.2 C32.2 C33.2 C34.2 C35.2 C36.2 C37.2 C38.2 C39.2 C40.2 C42.1 C43.2 D8.2 D9.2 J1.A1 J1.A12 J1.B1 J1.B12 J1.M1 J1.M2 J1.S1 J1.S2 J1.S3 J1.S4 pad.2@1690,2060 Q7.1 Q7.2 Q7.3 R36.1 R38.1 R40.1 R41.1 TP4.1 U6.4 U6.17 U6.18 U6.25@1005,2360 U7.2 | length 620
  Top Layer w40: pad.2@1690,2060 1690,2235
  Signal Layer 1 w40: pad.2@1690,2060 1690,2195
  Signal Layer 2 w40: pad.2@1690,2060 1690,2210
  Bottom Layer w40: pad.2@1690,2060 1690,2220
  other v1: 995,2205 355,2230 355,2275 355,2320 1255,2330 355,2365 840,2380 945,2565 120,2585 1380,2615 407.5,2635.75
  other v3: 1005,2316.69 961.69,2360 1005,2360 1048.31,2360 1005,2403.31
SGND1: C15.1 C26.1 pad.0@1690,1820 R31.2 U5.3
  other v1: 1480.51,1865
Vaux: C20.1 D3.2 D101.2 R20.2 T1.6 | length 1509.7
  Signal Layer 1 w8: T1.6@636.32,870.68 775.99,731.01 799.98,731.01 810.3,720.69 1128.83,720.69 1453.87,1045.72 1495.72,1045.72 1580,1130 v1(1645,1130)
  Bottom Layer w8: v1(1645,1130) C20.1@1675,1130 R20.2@1675,1170
  Bottom Layer w20: D3.2@547.05,870 D3.2@547.73,870.68 ; D101.2@548.78,980 548.78,871.73 D3.2@547.73,870.68 ; T1.6@636.32,870.68 D3.2@547.73,870.68
Vbk: C16.1 C44.1 D4.1 Q3.3 R17.1 R104.2 | length 1688.6
  Signal Layer 2 w12: v2(445,738.15) 790.01,738.15 809.47,718.69 833.39,718.69 852.86,738.15 1130.55,738.15 v2(1465,1072.6)
  Bottom Layer w12: R17.1@200,860 241.69,860 Q3.3@290,811.69 335,766.69 C44.1@335,738.15 ; C16.1@255,709.37 283.78,738.15 C44.1@335,738.15 ; D4.1@502.91,755.78 485.28,738.15 v2(445,738.15) C44.1@335,738.15 ; v2(1465,1072.6) 1495.65,1072.6 R104.2@1505.5,1082.45
Vbulk: C2.1 C4.2 C5.2 C6.1 C7.1 C8.1 C9.1 L1.2 R5.2 T1.1 | length 150.4
  Bottom Layer w70: T1.1@832.89,969.68 983.26,969.68
VBUS: C29.1 D8.1 J1.A4 J1.A9 J1.B4 J1.B9 R34.1 R39.2 TP3.1 U6.21 | length 476.6
  Top Layer w8: J1.A4@1483.46,2470.79 1485.37,2472.69 1533.07,2472.69 J1.B9@1533.07,2472.76 ; J1.A9@1483.46,2569.21 1485.37,2567.31 1533.07,2567.31 J1.B4@1533.07,2567.24
  Signal Layer 1 w8: v1(1005,2480) 1076.99,2480 1093.87,2463.13 1258.13,2463.13 v1(1305,2510)
  Bottom Layer w8: U6.21@995.16,2434.8 995.16,2470.16 v1(1005,2480)
  other v1: 1430,2445 1345,2510
Vdd_drv: C18.2 C102.1 D2.2 R100.2 U1.4 U3.1 | length 1258.3
  Signal Layer 1 w12: v2(192.25,1082.41) 192.25,1161.35 v2(344.88,1313.98)
  Bottom Layer w12: R100.2@140,1095.5 140,1094.12 180.54,1094.12 v2(192.25,1082.41) ; U1.4@247.88,1314.92 C18.2@302.31,1314.93 343.92,1314.93 v2(344.88,1313.98) 368.91,1313.98 544.94,1490 942.83,1490 982.81,1450.02 1005.95,1450.02 U3.1@1046.32,1409.66
Vdd_pri: C10.1 C17.1 C22.2 D3.1 Q3.2 R6.2 U1.3 U2.15 | length 2520.2
  Signal Layer 2 w10: v2(296.61,1013.66) 220.13,1090.15 220.13,1126.37 183.9,1162.6 v2(183.9,1315) 307.82,1315 317,1305.82 317,1302.43 333.33,1286.1 372.75,1286.1 564.89,1478.24 981.96,1478.24 1027.03,1433.17 1158.4,1433.17 1203.47,1478.24 1536.4,1478.24 1536.76,1477.87 1656.55,1477.87 1682.26,1452.16 v2(1689.47,1452.16)
  Bottom Layer w8: C10.1@1721.76,1445 1724.84,1441.92 U2.15@1724.84,1395.12
  Bottom Layer w10: R6.2@50.63,1240.12 50.63,1292.94 72.6,1314.91 C17.1@94.7,1314.91 U1.3@139.61,1314.92 139.69,1315 v2(183.9,1315) ; v2(296.61,1013.66) 324.8,985.48 C22.2@324.8,960.78 ; C22.2@333.81,955.47 327.4,949.06 Q3.2@327.4,898.31 410.26,898.31 410.26,888.68 D3.1@428.94,870 ; v2(1689.47,1452.16) 1714.61,1452.16 C10.1@1721.76,1445
VDRN: C41.1 D9.1 pad.2@180,2060 Q7.5 Q7.6 Q7.7 Q7.8 Q7.9 R42.2 | length 283.9
  Top Layer w8: v7(115,2350) R42.2@115,2425
  Bottom Layer w100: Q7.9@158.43,2260 180,2238.43 pad.2@180,2060
VDRN1: pad.0@180,1820 T1.B
VN: C35.1 C38.1 C39.1 C40.1 L3.1 L100.1 pad.2@500,2060 | length 206.1
  Top Layer w25: v1(705,2565.51) L100.1@705,2631.14
  Bottom Layer w100: pad.2@500,2060 500,2181.85 C35.1@513.15,2195
VN1: pad.0@500,1820 T1.A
